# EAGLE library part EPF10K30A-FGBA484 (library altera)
EPF10K30 FLEX 10K family
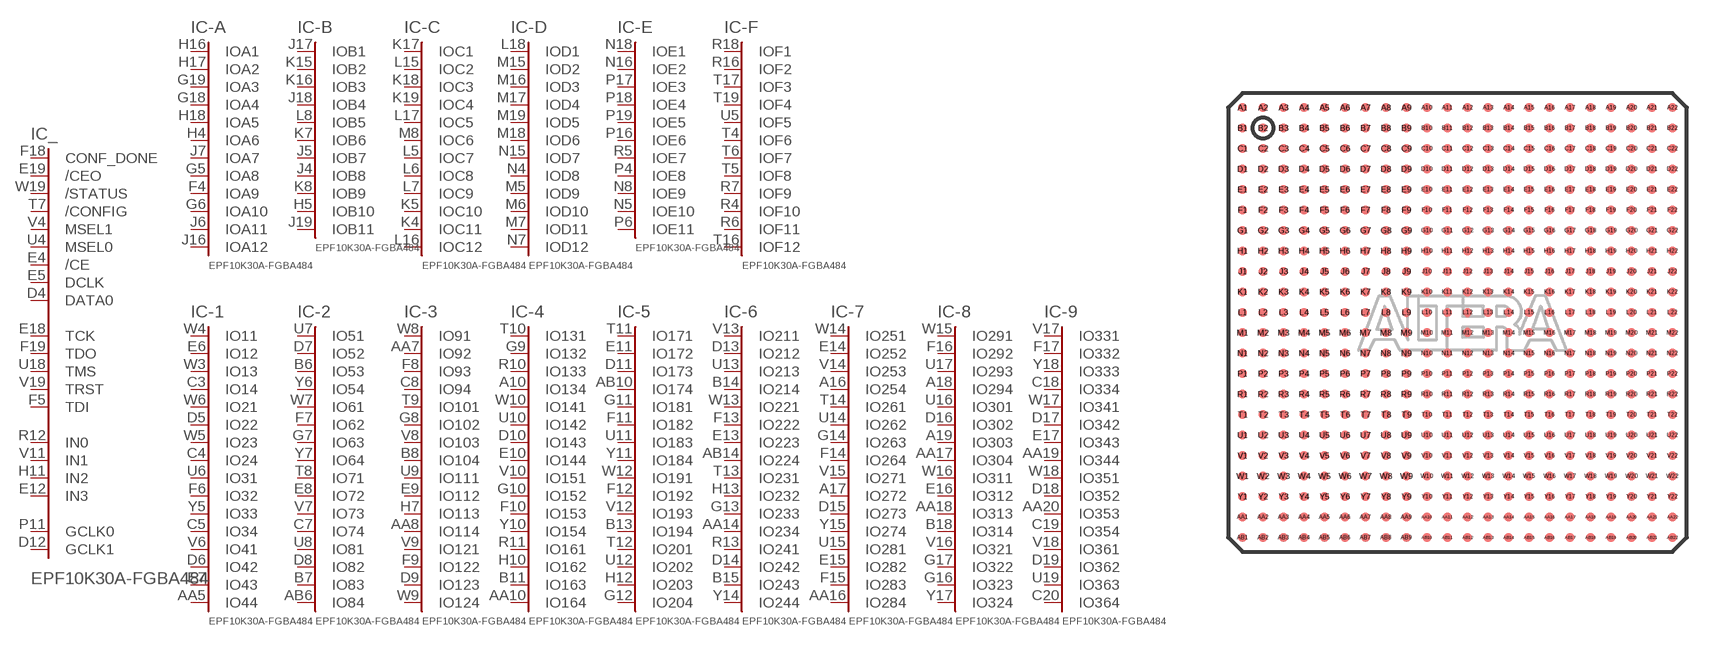
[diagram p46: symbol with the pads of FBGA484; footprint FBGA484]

Designator prefix IC; gates _=100R240C -A=A12 -B=B11 -C=C12 -D=D12 -E=E11 -F=F12 -1=IO44 -2=IO84 -3=IO124 -4=IO164 -5=IO204 -6=IO244 -7=IO284 -8=IO324 -9=IO364 G1=GND G2=GND G3=GND G4=GND G5=GND G6=GND G7=GND G8=GND G9=GND G10=GND G11=GND G12=GND G13=GND G14=GND G15=GND G16=GND G17=GND G18=GND G19=GND G20=GND G21=GND G22=GND G23=GND G24=GND G25=GND G26=GND G27=GND G28=GND G29=GND G30=GND G31=GND G32=GND G33=GND G34=GND G35=GND G36=GND G37=GND G38=GND G39=GND G40=GND G41=GND G42=GND G43=GND G44=GND G45=GND G46=GND G47=GND G48=GND G49=GND NC1=NC NC2=NC NC3=NC NC4=NC NC5=NC NC6=NC NC7=NC NC8=NC NC9=NC NC10=NC NC11=NC NC12=NC NC13=NC NC14=NC NC15=NC NC16=NC NC17=NC NC18=NC NC19=NC NC20=NC NC21=NC NC22=NC NC23=NC NC24=NC NC25=NC NC26=NC NC27=NC NC28=NC NC29=NC NC30=NC NC31=NC NC32=NC NC33=NC NC34=NC NC35=NC NC36=NC NC37=NC NC38=NC NC39=NC NC40=NC NC41=NC NC42=NC NC43=NC NC44=NC NC45=NC NC46=NC NC47=NC NC48=NC NC49=NC NC50=NC NC51=NC NC52=NC NC53=NC NC54=NC NC55=NC NC56=NC NC57=NC NC58=NC NC59=NC NC60=NC NC61=NC NC62=NC NC63=NC NC64=NC NC65=NC NC66=NC NC67=NC NC68=NC NC69=NC NC70=NC NC71=NC NC72=NC NC73=NC NC74=NC NC75=NC NC76=NC NC77=NC NC78=NC NC79=NC NC80=NC NC81=NC NC82=NC NC83=NC NC84=NC NC85=NC NC86=NC NC87=NC NC88=NC NC89=NC NC90=NC NC91=NC NC92=NC NC93=NC NC94=NC NC95=NC NC96=NC NC97=NC NC98=NC NC99=NC NC100=NC NC101=NC NC102=NC NC103=NC NC104=NC NC105=NC NC106=NC NC107=NC NC108=NC NC109=NC NC110=NC NC111=NC NC112=NC NC113=NC NC114=NC NC115=NC NC116=NC NC117=NC NC118=NC NC119=NC NC120=NC NC121=NC NC122=NC NC123=NC NC124=NC NC125=NC NC126=NC NC127=NC NC128=NC NC129=NC NC130=NC NC131=NC NC132=NC NC133=NC NC134=NC NC135=NC NC136=NC NC137=NC NC138=NC NC139=NC NC140=NC NC141=NC NC142=NC NC143=NC NC144=NC NC145=NC NC146=NC NC147=NC NC148=NC NC149=NC V1=VCCINT V2=VCCINT V3=VCCINT V4=VCCINT V5=VCCINT V6=VCCINT V7=VCCINT V8=VCCINT V9=VCCINT V10=VCCINT V11=VCCINT V12=VCCINT V13=VCCINT V14=VCCINT V15=VCCINT V16=VCCINT V17=VCCINT V18=VCCINT V19=VCCINT V20=VCCINT V21=VCCINT V22=VCCINT V23=VCCINT VO1=VCCIO VO2=VCCIO VO3=VCCIO VO4=VCCIO VO5=VCCIO VO6=VCCIO VO7=VCCIO VO8=VCCIO VO9=VCCIO VO10=VCCIO VO11=VCCIO VO12=VCCIO VO13=VCCIO VO14=VCCIO VO15=VCCIO VO16=VCCIO VO17=VCCIO VO18=VCCIO VO19=VCCIO VO20=VCCIO VO21=VCCIO VO22=VCCIO VO23=VCCIO VO24=VCCIO VO25=VCCIO VO26=VCCIO VO27=VCCIO VO28=VCCIO VO29=VCCIO

## EPF10K30A-FGBA484 (MPN: EPF10K30AFC484-1; OC_FARNELL: unknown; OC_NEWARK: 51R8942)  [FBGA484]
A1  G6:GND  pwr
A2  NC25:NC  nc
A3  NC26:NC  nc
A4  NC27:NC  nc
A5  NC28:NC  nc
A6  VO2:VCCIO  pwr
A7  NC29:NC  nc
A8  G7:GND  pwr
A9  NC30:NC  nc
A10  -4:IO134
A11  NC31:NC  nc
A12  NC32:NC  nc
A13  VO3:VCCIO  pwr
A14  NC33:NC  nc
A15  NC34:NC  nc
A16  -7:IO254
A17  -7:IO272
A18  -8:IO294
A19  -8:IO303
A20  NC35:NC  nc
A21  NC36:NC  nc
A22  G8:GND  pwr
AA1  G1:GND  pwr
AA2  NC1:NC  nc
AA3  NC2:NC  nc
AA4  NC3:NC  nc
AA5  -1:IO44
AA6  G2:GND  pwr
AA7  -3:IO92
AA8  -3:IO114
AA9  NC4:NC  nc
AA10  -4:IO164
AA11  NC5:NC  nc
AA12  V1:VCC  pwr
AA13  NC6:NC  nc
AA14  -6:IO234
AA15  NC7:NC  nc
AA16  -7:IO284
AA17  -8:IO304
AA18  -8:IO313
AA19  -9:IO344
AA20  -9:IO353
AA21  NC8:NC  nc
AA22  G3:GND  pwr
AB1  NC9:NC  nc
AB2  NC10:NC  nc
AB3  NC11:NC  nc
AB4  NC12:NC  nc
AB5  NC13:NC  nc
AB6  -2:IO84
AB7  NC14:NC  nc
AB8  NC15:NC  nc
AB9  NC16:NC  nc
AB10  -5:IO174
AB11  G4:GND  pwr
AB12  NC17:NC  nc
AB13  VO1:VCCIO  pwr
AB14  -6:IO224
AB15  NC18:NC  nc
AB16  G5:GND  pwr
AB17  NC19:NC  nc
AB18  NC20:NC  nc
AB19  NC21:NC  nc
AB20  NC22:NC  nc
AB21  NC23:NC  nc
AB22  NC24:NC  nc
B1  G9:GND  pwr
B2  G10:GND  pwr
B3  NC37:NC  nc
B4  NC38:NC  nc
B5  VO4:VCCIO  pwr
B6  -2:IO53
B7  -2:IO83
B8  -3:IO104
B9  NC39:NC  nc
B10  NC40:NC  nc
B11  -4:IO163
B12  NC41:NC  nc
B13  -5:IO194
B14  -6:IO214
B15  -6:IO243
B16  NC42:NC  nc
B17  G11:GND  pwr
B18  -8:IO314
B19  NC43:NC  nc
B20  NC44:NC  nc
B21  G12:GND  pwr
B22  G13:GND  pwr
C1  NC45:NC  nc
C2  G14:GND  pwr
C3  -1:IO14
C4  -1:IO24
C5  -1:IO34
C6  NC46:NC  nc
C7  -2:IO74
C8  -3:IO94
C9  NC47:NC  nc
C10  NC48:NC  nc
C11  V2:VCC  pwr
C12  NC49:NC  nc
C13  NC50:NC  nc
C14  NC51:NC  nc
C15  V3:VCC  pwr
C16  NC52:NC  nc
C17  NC53:NC  nc
C18  -9:IO334
C19  -9:IO354
C20  -9:IO364
C21  G15:GND  pwr
C22  NC54:NC  nc
D1  NC55:NC  nc
D2  NC56:NC  nc
D3  NC57:NC  nc
D4  _:DATA0  in
D5  -1:IO22
D6  -1:IO42
D7  -2:IO52
D8  -2:IO82
D9  -3:IO123
D10  -4:IO143
D11  -5:IO173
D12  _:GCLK1  in
D13  -6:IO212
D14  -6:IO242
D15  -7:IO273
D16  -8:IO302
D17  -9:IO342
D18  -9:IO352
D19  -9:IO362
D20  NC58:NC  nc
D21  NC59:NC  nc
D22  NC60:NC  nc
E1  VO5:VCCIO  pwr
E2  NC61:NC  nc
E3  NC62:NC  nc
E4  _:/CE  in
E5  _:DCLK  in
E6  -1:IO12
E7  -1:IO43
E8  -2:IO72
E9  -3:IO112
E10  -4:IO144
E11  -5:IO172
E12  _:IN3  in
E13  -6:IO223
E14  -7:IO252
E15  -7:IO282
E16  -8:IO312
E17  -9:IO343
E18  _:TCK
E19  _:/CEO  in
E20  NC63:NC  nc
E21  G16:GND  pwr
E22  NC64:NC  nc
F1  NC65:NC  nc
F2  NC66:NC  nc
F3  NC67:NC  nc
F4  -A:IOA9
F5  _:TDI
F6  -1:IO32
F7  -2:IO62
F8  -3:IO93
F9  -3:IO122
F10  -4:IO153
F11  -5:IO182
F12  -5:IO192
F13  -6:IO222
F14  -7:IO264
F15  -7:IO283
F16  -8:IO292
F17  -9:IO332
F18  _:CONF_DONE  in
F19  _:TDO
F20  NC68:NC  nc
F21  NC69:NC  nc
F22  NC70:NC  nc
G1  VO6:VCCIO  pwr
G2  NC71:NC  nc
G3  G17:GND  pwr
G4  NC72:NC  nc
G5  -A:IOA8
G6  -A:IOA10
G7  -2:IO63
G8  -3:IO102
G9  -4:IO132
G10  -4:IO152
G11  -5:IO181
G12  -5:IO204
G13  -6:IO233
G14  -7:IO263
G15  VO7:VCCIO  pwr
G16  -8:IO323
G17  -8:IO322
G18  -A:IOA4
G19  -A:IOA3
G20  NC73:NC  nc
G21  G18:GND  pwr
G22  NC74:NC  nc
H1  NC75:NC  nc
H2  G19:GND  pwr
H3  NC76:NC  nc
H4  -A:IOA6
H5  -B:IOB10
H6  NC77:NC  nc
H7  -3:IO113
H8  G20:GND  pwr
H9  VO8:VCCIO  pwr
H10  -4:IO162
H11  _:IN2  in
H12  -5:IO203
H13  -6:IO232
H14  V4:VCC  pwr
H15  G21:GND  pwr
H16  -A:IOA1
H17  -A:IOA2
H18  -A:IOA5
H19  NC78:NC  nc
H20  VO9:VCCIO  pwr
H21  NC79:NC  nc
H22  NC80:NC  nc
J1  NC81:NC  nc
J2  NC82:NC  nc
J3  NC83:NC  nc
J4  -B:IOB8
J5  -B:IOB7
J6  -A:IOA11
J7  -A:IOA7
J8  V5:VCC  pwr
J9  G22:GND  pwr
J10  V6:VCC  pwr
J11  VO10:VCCIO  pwr
J12  V7:VCC  pwr
J13  VO11:VCCIO  pwr
J14  G23:GND  pwr
J15  V8:VCC  pwr
J16  -A:IOA12
J17  -B:IOB1
J18  -B:IOB4
J19  -B:IOB11
J20  G24:GND  pwr
J21  NC84:NC  nc
J22  NC85:NC  nc
K1  NC86:NC  nc
K2  NC87:NC  nc
K3  G25:GND  pwr
K4  -C:IOC11
K5  -C:IOC10
K6  NC88:NC  nc
K7  -B:IOB6
K8  -B:IOB9
K9  VO12:VCCIO  pwr
K10  G26:GND  pwr
K11  VO13:VCCIO  pwr
K12  G27:GND  pwr
K13  G28:GND  pwr
K14  VO14:VCCIO  pwr
K15  -B:IOB2
K16  -B:IOB3
K17  -C:IOC1
K18  -C:IOC3
K19  -C:IOC4
K20  VO15:VCCIO  pwr
K21  NC89:NC  nc
K22  NC90:NC  nc
L1  NC91:NC  nc
L2  NC92:NC  nc
L3  NC93:NC  nc
L4  NC94:NC  nc
L5  -C:IOC7
L6  -C:IOC8
L7  -C:IOC9
L8  -B:IOB5
L9  V9:VCC  pwr
L10  V10:VCC  pwr
L11  G29:GND  pwr
L12  G30:GND  pwr
L13  V11:VCC  pwr
L14  VO16:VCCIO  pwr
L15  -C:IOC2
L16  -C:IOC12
L17  -C:IOC5
L18  -D:IOD1
L19  NC95:NC  nc
L20  NC96:NC  nc
L21  NC97:NC  nc
L22  NC98:NC  nc
M1  NC99:NC  nc
M2  NC100:NC  nc
M3  NC101:NC  nc
M4  NC102:NC  nc
M5  -D:IOD9
M6  -D:IOD10
M7  -D:IOD11
M8  -C:IOC6
M9  VO17:VCCIO  pwr
M10  V12:VCC  pwr
M11  G31:GND  pwr
M12  G32:GND  pwr
M13  V13:VCC  pwr
M14  V14:VCC  pwr
M15  -D:IOD2
M16  -D:IOD3
M17  -D:IOD4
M18  -D:IOD6
M19  -D:IOD5
M20  G33:GND  pwr
M21  NC103:NC  nc
M22  NC104:NC  nc
N1  NC105:NC  nc
N2  NC106:NC  nc
N3  VO18:VCCIO  pwr
N4  -D:IOD8
N5  -E:IOE10
N6  NC107:NC  nc
N7  -D:IOD12
N8  -E:IOE9
N9  VO19:VCCIO  pwr
N10  G34:GND  pwr
N11  VO20:VCCIO  pwr
N12  V15:VCC  pwr
N13  G35:GND  pwr
N14  VO21:VCCIO  pwr
N15  -D:IOD7
N16  -E:IOE2
N17  NC108:NC  nc
N18  -E:IOE1
N19  NC109:NC  nc
N20  VO22:VCCIO  pwr
N21  NC111:NC  nc
N22  NC112:NC  nc
P1  NC113:NC  nc
P2  NC114:NC  nc
P3  NC115:NC  nc
P4  -E:IOE8
P5  NC116:NC  nc
P6  -E:IOE11
P7  NC117:NC  nc
P8  V16:VCC  pwr
P9  G36:GND  pwr
P10  V17:VCC  pwr
P11  _:GCLK0  in
P12  V18:VCC  pwr
P13  VO23:VCCIO  pwr
P14  G37:GND  pwr
P15  V19:VCC  pwr
P16  -E:IOE6
P17  -E:IOE3
P18  -E:IOE4
P19  -E:IOE5
P20  NC118:NC  nc
P21  NC119:NC  nc
P22  NC120:NC  nc
R1  VO24:VCCIO  pwr
R2  NC121:NC  nc
R3  NC122:NC  nc
R4  -F:IOF10
R5  -E:IOE7
R6  -F:IOF11
R7  -F:IOF9
R8  G38:GND  pwr
R9  VO25:VCCIO  pwr
R10  -4:IO133
R11  -4:IO161
R12  _:IN0  in
R13  -6:IO241
R14  V20:VCC  pwr
R15  G39:GND  pwr
R16  -F:IOF2
R17  NC123:NC  nc
R18  -F:IOF1
R19  NC124:NC  nc
R20  NC125:NC  nc
R21  NC126:NC  nc
R22  G40:GND  pwr
T1  G41:GND  pwr
T2  NC127:NC  nc
T3  VO26:VCCIO  pwr
T4  -F:IOF6
T5  -F:IOF8
T6  -F:IOF7
T7  _:/CONFIG  in
T8  -2:IO71
T9  -3:IO101
T10  -4:IO131
T11  -5:IO171
T12  -5:IO201
T13  -6:IO231
T14  -7:IO261
T15  VO27:VCCIO  pwr
T16  -F:IOF12
T17  -F:IOF3
T18  NC128:NC  nc
T19  -F:IOF4
T20  NC129:NC  nc
T21  NC130:NC  nc
T22  VO28:VCCIO  pwr
U1  NC131:NC  nc
U2  NC132:NC  nc
U3  NC133:NC  nc
U4  _:MSEL0  in
U5  -F:IOF5
U6  -1:IO31
U7  -2:IO51
U8  -2:IO81
U9  -3:IO111
U10  -4:IO142
U11  -5:IO183
U12  -5:IO202
U13  -6:IO213
U14  -7:IO262
U15  -7:IO281
U16  -8:IO301
U17  -8:IO293
U18  _:TMS
U19  -9:IO363
U20  NC134:NC  nc
U21  NC110:NC  nc
U22  NC135:NC  nc
V1  NC136:NC  nc
V2  NC137:NC  nc
V3  G42:GND  pwr
V4  _:MSEL1  in
V5  V21:VCC  pwr
V6  -1:IO41
V7  -2:IO73
V8  -3:IO103
V9  -3:IO121
V10  -4:IO151
V11  _:IN1  in
V12  -5:IO193
V13  -6:IO211
V14  -7:IO253
V15  -7:IO271
V16  -8:IO321
V17  -9:IO331
V18  -9:IO361
V19  _:TRST
V20  NC138:NC  nc
V21  NC139:NC  nc
V22  VO29:VCCIO  pwr
W1  NC140:NC  nc
W2  NC141:NC  nc
W3  -1:IO13
W4  -1:IO11
W5  -1:IO23
W6  -1:IO21
W7  -2:IO61
W8  -3:IO91
W9  -3:IO124
W10  -4:IO141
W11  G43:GND  pwr
W12  -5:IO191
W13  -6:IO221
W14  -7:IO251
W15  -8:IO291
W16  -8:IO311
W17  -9:IO341
W18  -9:IO351
W19  _:/STATUS  in
W20  G44:GND  pwr
W21  V22:VCC  pwr
W22  NC142:NC  nc
Y1  G45:GND  pwr
Y2  G46:GND  pwr
Y3  G47:GND  pwr
Y4  NC143:NC  nc
Y5  -1:IO33
Y6  -2:IO54
Y7  -2:IO64
Y8  V23:VCC  pwr
Y9  NC144:NC  nc
Y10  -4:IO154
Y11  -5:IO184
Y12  NC145:NC  nc
Y13  NC146:NC  nc
Y14  -6:IO244
Y15  -7:IO274
Y16  NC147:NC  nc
Y17  -8:IO324
Y18  -9:IO333
Y19  NC148:NC  nc
Y20  NC149:NC  nc
Y21  G48:GND  pwr
Y22  G49:GND  pwr

## Footprint FBGA484 (pad centres in mm)
Fine Ball Grid Array
smd 0.45 x 0.45: A1 -10.5,10.5; A2 -9.5,10.5; A3 -8.5,10.5; A4 -7.5,10.5; A5 -6.5,10.5; A6 -5.5,10.5; A7 -4.5,10.5; A8 -3.5,10.5; A9 -2.5,10.5; A10 -1.5,10.5; A11 -0.5,10.5; A12 0.5,10.5; A13 1.5,10.5; A14 2.5,10.5; A15 3.5,10.5; A16 4.5,10.5; A17 5.5,10.5; A18 6.5,10.5; A19 7.5,10.5; A20 8.5,10.5; A21 9.5,10.5; A22 10.5,10.5; AA1 -10.5,-9.5; AA2 -9.5,-9.5; AA3 -8.5,-9.5; AA4 -7.5,-9.5; AA5 -6.5,-9.5; AA6 -5.5,-9.5; AA7 -4.5,-9.5; AA8 -3.5,-9.5; AA9 -2.5,-9.5; AA10 -1.5,-9.5; AA11 -0.5,-9.5; AA12 0.5,-9.5; AA13 1.5,-9.5; AA14 2.5,-9.5; AA15 3.5,-9.5; AA16 4.5,-9.5; AA17 5.5,-9.5; AA18 6.5,-9.5; AA19 7.5,-9.5; AA20 8.5,-9.5; AA21 9.5,-9.5; AA22 10.5,-9.5; AB1 -10.5,-10.5; AB2 -9.5,-10.5; AB3 -8.5,-10.5; AB4 -7.5,-10.5; AB5 -6.5,-10.5; AB6 -5.5,-10.5; AB7 -4.5,-10.5; AB8 -3.5,-10.5; AB9 -2.5,-10.5; AB10 -1.5,-10.5; AB11 -0.5,-10.5; AB12 0.5,-10.5; AB13 1.5,-10.5; AB14 2.5,-10.5; AB15 3.5,-10.5; AB16 4.5,-10.5; AB17 5.5,-10.5; AB18 6.5,-10.5; AB19 7.5,-10.5; AB20 8.5,-10.5; AB21 9.5,-10.5; AB22 10.5,-10.5; B1 -10.5,9.5; B2 -9.5,9.5; B3 -8.5,9.5; B4 -7.5,9.5; B5 -6.5,9.5; B6 -5.5,9.5; B7 -4.5,9.5; B8 -3.5,9.5; B9 -2.5,9.5; B10 -1.5,9.5; B11 -0.5,9.5; B12 0.5,9.5; B13 1.5,9.5; B14 2.5,9.5; B15 3.5,9.5; B16 4.5,9.5; B17 5.5,9.5; B18 6.5,9.5; B19 7.5,9.5; B20 8.5,9.5; B21 9.5,9.5; B22 10.5,9.5; C1 -10.5,8.5; C2 -9.5,8.5; C3 -8.5,8.5; C4 -7.5,8.5; C5 -6.5,8.5; C6 -5.5,8.5; C7 -4.5,8.5; C8 -3.5,8.5; C9 -2.5,8.5; C10 -1.5,8.5; C11 -0.5,8.5; C12 0.5,8.5; C13 1.5,8.5; C14 2.5,8.5; C15 3.5,8.5; C16 4.5,8.5; C17 5.5,8.5; C18 6.5,8.5; C19 7.5,8.5; C20 8.5,8.5; C21 9.5,8.5; C22 10.5,8.5; D1 -10.5,7.5; D2 -9.5,7.5; D3 -8.5,7.5; D4 -7.5,7.5; D5 -6.5,7.5; D6 -5.5,7.5; D7 -4.5,7.5; D8 -3.5,7.5; D9 -2.5,7.5; D10 -1.5,7.5; D11 -0.5,7.5; D12 0.5,7.5; D13 1.5,7.5; D14 2.5,7.5; D15 3.5,7.5; D16 4.5,7.5; D17 5.5,7.5; D18 6.5,7.5; D19 7.5,7.5; D20 8.5,7.5; D21 9.5,7.5; D22 10.5,7.5; E1 -10.5,6.5; E2 -9.5,6.5; E3 -8.5,6.5; E4 -7.5,6.5; E5 -6.5,6.5; E6 -5.5,6.5; E7 -4.5,6.5; E8 -3.5,6.5; E9 -2.5,6.5; E10 -1.5,6.5; E11 -0.5,6.5; E12 0.5,6.5; E13 1.5,6.5; E14 2.5,6.5; E15 3.5,6.5; E16 4.5,6.5; E17 5.5,6.5; E18 6.5,6.5; E19 7.5,6.5; E20 8.5,6.5; E21 9.5,6.5; E22 10.5,6.5; F1 -10.5,5.5; F2 -9.5,5.5; F3 -8.5,5.5; F4 -7.5,5.5; F5 -6.5,5.5; F6 -5.5,5.5; F7 -4.5,5.5; F8 -3.5,5.5; F9 -2.5,5.5; F10 -1.5,5.5; F11 -0.5,5.5; F12 0.5,5.5; F13 1.5,5.5; F14 2.5,5.5; F15 3.5,5.5; F16 4.5,5.5; F17 5.5,5.5; F18 6.5,5.5; F19 7.5,5.5; F20 8.5,5.5; F21 9.5,5.5; F22 10.5,5.5; G1 -10.5,4.5; G2 -9.5,4.5; G3 -8.5,4.5; G4 -7.5,4.5; G5 -6.5,4.5; G6 -5.5,4.5; G7 -4.5,4.5; G8 -3.5,4.5; G9 -2.5,4.5; G10 -1.5,4.5; G11 -0.5,4.5; G12 0.5,4.5; G13 1.5,4.5; G14 2.5,4.5; G15 3.5,4.5; G16 4.5,4.5; G17 5.5,4.5; G18 6.5,4.5; G19 7.5,4.5; G20 8.5,4.5; G21 9.5,4.5; G22 10.5,4.5; H1 -10.5,3.5; H2 -9.5,3.5; H3 -8.5,3.5; H4 -7.5,3.5; H5 -6.5,3.5; H6 -5.5,3.5; H7 -4.5,3.5; H8 -3.5,3.5; H9 -2.5,3.5; H10 -1.5,3.5; H11 -0.5,3.5; H12 0.5,3.5; H13 1.5,3.5; H14 2.5,3.5; H15 3.5,3.5; H16 4.5,3.5; H17 5.5,3.5; H18 6.5,3.5; H19 7.5,3.5; H20 8.5,3.5; H21 9.5,3.5; H22 10.5,3.5; J1 -10.5,2.5; J2 -9.5,2.5; J3 -8.5,2.5; J4 -7.5,2.5; J5 -6.5,2.5; J6 -5.5,2.5; J7 -4.5,2.5; J8 -3.5,2.5; J9 -2.5,2.5; J10 -1.5,2.5; J11 -0.5,2.5; J12 0.5,2.5; J13 1.5,2.5; J14 2.5,2.5; J15 3.5,2.5; J16 4.5,2.5; J17 5.5,2.5; J18 6.5,2.5; J19 7.5,2.5; J20 8.5,2.5; J21 9.5,2.5; J22 10.5,2.5; K1 -10.5,1.5; K2 -9.5,1.5; K3 -8.5,1.5; K4 -7.5,1.5; K5 -6.5,1.5; K6 -5.5,1.5; K7 -4.5,1.5; K8 -3.5,1.5; K9 -2.5,1.5; K10 -1.5,1.5; K11 -0.5,1.5; K12 0.5,1.5; K13 1.5,1.5; K14 2.5,1.5; K15 3.5,1.5; K16 4.5,1.5; K17 5.5,1.5; K18 6.5,1.5; K19 7.5,1.5; K20 8.5,1.5; K21 9.5,1.5; K22 10.5,1.5; L1 -10.5,0.5; L2 -9.5,0.5; L3 -8.5,0.5; L4 -7.5,0.5; L5 -6.5,0.5; L6 -5.5,0.5; L7 -4.5,0.5; L8 -3.5,0.5; L9 -2.5,0.5; L10 -1.5,0.5; L11 -0.5,0.5; L12 0.5,0.5; L13 1.5,0.5; L14 2.5,0.5; L15 3.5,0.5; L16 4.5,0.5; L17 5.5,0.5; L18 6.5,0.5; L19 7.5,0.5; L20 8.5,0.5; L21 9.5,0.5; L22 10.5,0.5; M1 -10.5,-0.5; M2 -9.5,-0.5; M3 -8.5,-0.5; M4 -7.5,-0.5; M5 -6.5,-0.5; M6 -5.5,-0.5; M7 -4.5,-0.5; M8 -3.5,-0.5; M9 -2.5,-0.5; M10 -1.5,-0.5; M11 -0.5,-0.5; M12 0.5,-0.5; M13 1.5,-0.5; M14 2.5,-0.5; M15 3.5,-0.5; M16 4.5,-0.5; M17 5.5,-0.5; M18 6.5,-0.5; M19 7.5,-0.5; M20 8.5,-0.5; M21 9.5,-0.5; M22 10.5,-0.5; N1 -10.5,-1.5; N2 -9.5,-1.5; N3 -8.5,-1.5; N4 -7.5,-1.5; N5 -6.5,-1.5; N6 -5.5,-1.5; N7 -4.5,-1.5; N8 -3.5,-1.5; N9 -2.5,-1.5; N10 -1.5,-1.5; N11 -0.5,-1.5; N12 0.5,-1.5; N13 1.5,-1.5; N14 2.5,-1.5; N15 3.5,-1.5; N16 4.5,-1.5; N17 5.5,-1.5; N18 6.5,-1.5; N19 7.5,-1.5; N20 8.5,-1.5; N21 9.5,-1.5; N22 10.5,-1.5; P1 -10.5,-2.5; P2 -9.5,-2.5; P3 -8.5,-2.5; P4 -7.5,-2.5; P5 -6.5,-2.5; P6 -5.5,-2.5; P7 -4.5,-2.5; P8 -3.5,-2.5; P9 -2.5,-2.5; P10 -1.5,-2.5; P11 -0.5,-2.5; P12 0.5,-2.5; P13 1.5,-2.5; P14 2.5,-2.5; P15 3.5,-2.5; P16 4.5,-2.5; P17 5.5,-2.5; P18 6.5,-2.5; P19 7.5,-2.5; P20 8.5,-2.5; P21 9.5,-2.5; P22 10.5,-2.5; R1 -10.5,-3.5; R2 -9.5,-3.5; R3 -8.5,-3.5; R4 -7.5,-3.5; R5 -6.5,-3.5; R6 -5.5,-3.5; R7 -4.5,-3.5; R8 -3.5,-3.5; R9 -2.5,-3.5; R10 -1.5,-3.5; R11 -0.5,-3.5; R12 0.5,-3.5; R13 1.5,-3.5; R14 2.5,-3.5; R15 3.5,-3.5; R16 4.5,-3.5; R17 5.5,-3.5; R18 6.5,-3.5; R19 7.5,-3.5; R20 8.5,-3.5; R21 9.5,-3.5; R22 10.5,-3.5; T1 -10.5,-4.5; T2 -9.5,-4.5; T3 -8.5,-4.5; T4 -7.5,-4.5; T5 -6.5,-4.5; T6 -5.5,-4.5; T7 -4.5,-4.5; T8 -3.5,-4.5; T9 -2.5,-4.5; T10 -1.5,-4.5; T11 -0.5,-4.5; T12 0.5,-4.5; T13 1.5,-4.5; T14 2.5,-4.5; T15 3.5,-4.5; T16 4.5,-4.5; T17 5.5,-4.5; T18 6.5,-4.5; T19 7.5,-4.5; T20 8.5,-4.5; T21 9.5,-4.5; T22 10.5,-4.5; U1 -10.5,-5.5; U2 -9.5,-5.5; U3 -8.5,-5.5; U4 -7.5,-5.5; U5 -6.5,-5.5; U6 -5.5,-5.5; U7 -4.5,-5.5; U8 -3.5,-5.5; U9 -2.5,-5.5; U10 -1.5,-5.5; U11 -0.5,-5.5; U12 0.5,-5.5; U13 1.5,-5.5; U14 2.5,-5.5; U15 3.5,-5.5; U16 4.5,-5.5; U17 5.5,-5.5; U18 6.5,-5.5; U19 7.5,-5.5; U20 8.5,-5.5; U21 9.5,-5.5; U22 10.5,-5.5; V1 -10.5,-6.5; V2 -9.5,-6.5; V3 -8.5,-6.5; V4 -7.5,-6.5; V5 -6.5,-6.5; V6 -5.5,-6.5; V7 -4.5,-6.5; V8 -3.5,-6.5; V9 -2.5,-6.5; V10 -1.5,-6.5; V11 -0.5,-6.5; V12 0.5,-6.5; V13 1.5,-6.5; V14 2.5,-6.5; V15 3.5,-6.5; V16 4.5,-6.5; V17 5.5,-6.5; V18 6.5,-6.5; V19 7.5,-6.5; V20 8.5,-6.5; V21 9.5,-6.5; V22 10.5,-6.5; W1 -10.5,-7.5; W2 -9.5,-7.5; W3 -8.5,-7.5; W4 -7.5,-7.5; W5 -6.5,-7.5; W6 -5.5,-7.5; W7 -4.5,-7.5; W8 -3.5,-7.5; W9 -2.5,-7.5; W10 -1.5,-7.5; W11 -0.5,-7.5; W12 0.5,-7.5; W13 1.5,-7.5; W14 2.5,-7.5; W15 3.5,-7.5; W16 4.5,-7.5; W17 5.5,-7.5; W18 6.5,-7.5; W19 7.5,-7.5; W20 8.5,-7.5; W21 9.5,-7.5; W22 10.5,-7.5; Y1 -10.5,-8.5; Y2 -9.5,-8.5; Y3 -8.5,-8.5; Y4 -7.5,-8.5; Y5 -6.5,-8.5; Y6 -5.5,-8.5; Y7 -4.5,-8.5; Y8 -3.5,-8.5; Y9 -2.5,-8.5; Y10 -1.5,-8.5; Y11 -0.5,-8.5; Y12 0.5,-8.5; Y13 1.5,-8.5; Y14 2.5,-8.5; Y15 3.5,-8.5; Y16 4.5,-8.5; Y17 5.5,-8.5; Y18 6.5,-8.5; Y19 7.5,-8.5; Y20 8.5,-8.5; Y21 9.5,-8.5; Y22 10.5,-8.5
